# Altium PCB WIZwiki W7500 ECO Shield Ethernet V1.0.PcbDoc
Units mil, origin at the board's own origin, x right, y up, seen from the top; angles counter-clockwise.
Board outline 2814.96 x 1259.84 mil, 2 copper layers (Top Layer, Bottom Layer); 18 components, 48 nets, 133 pads, 48 vias.
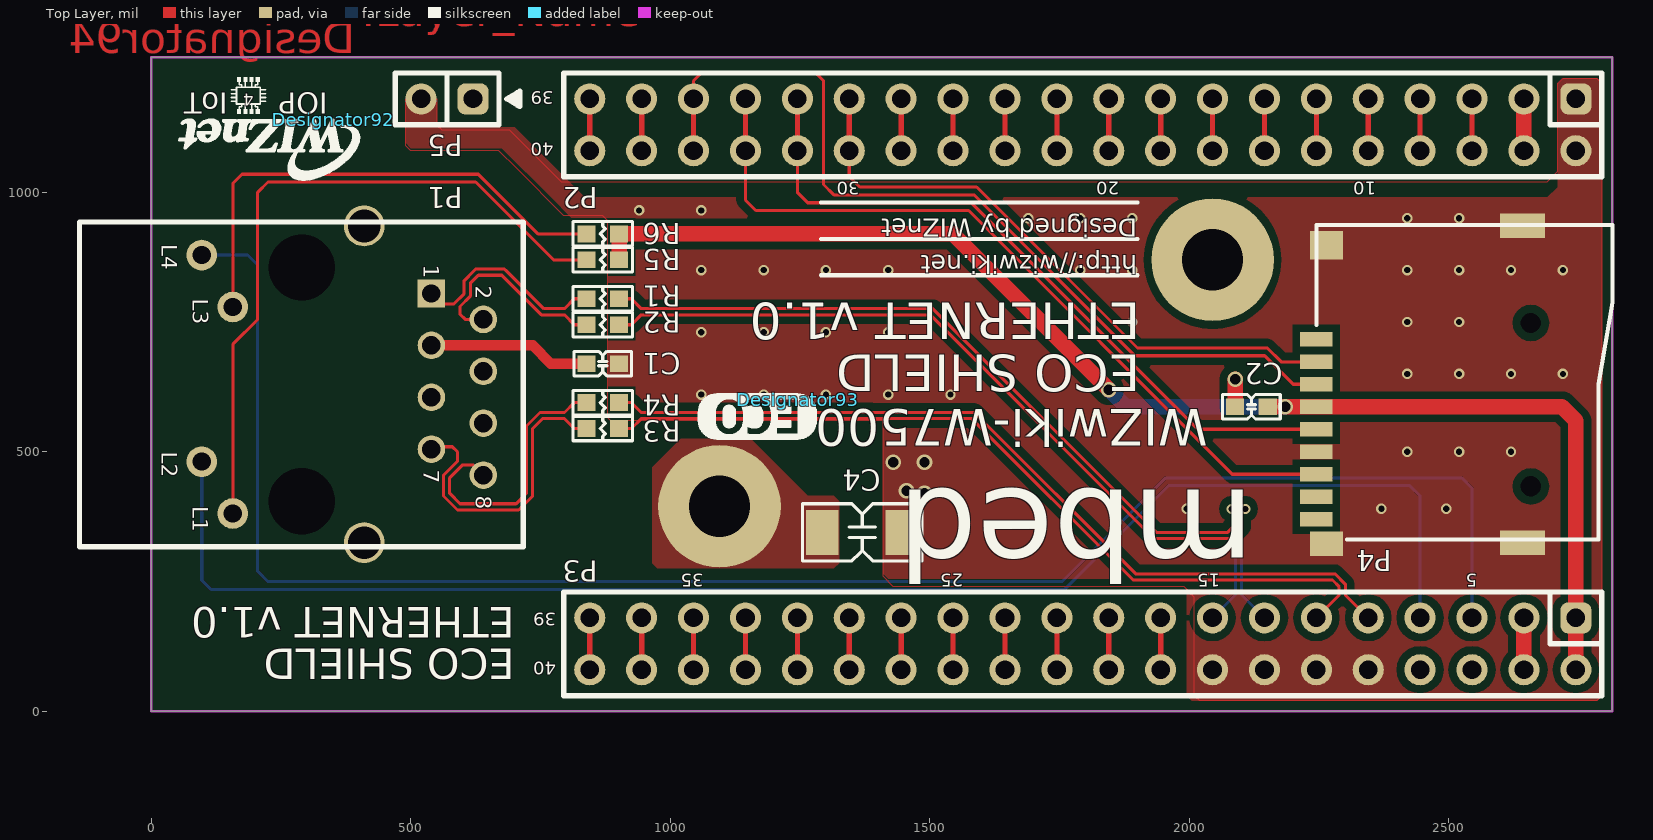
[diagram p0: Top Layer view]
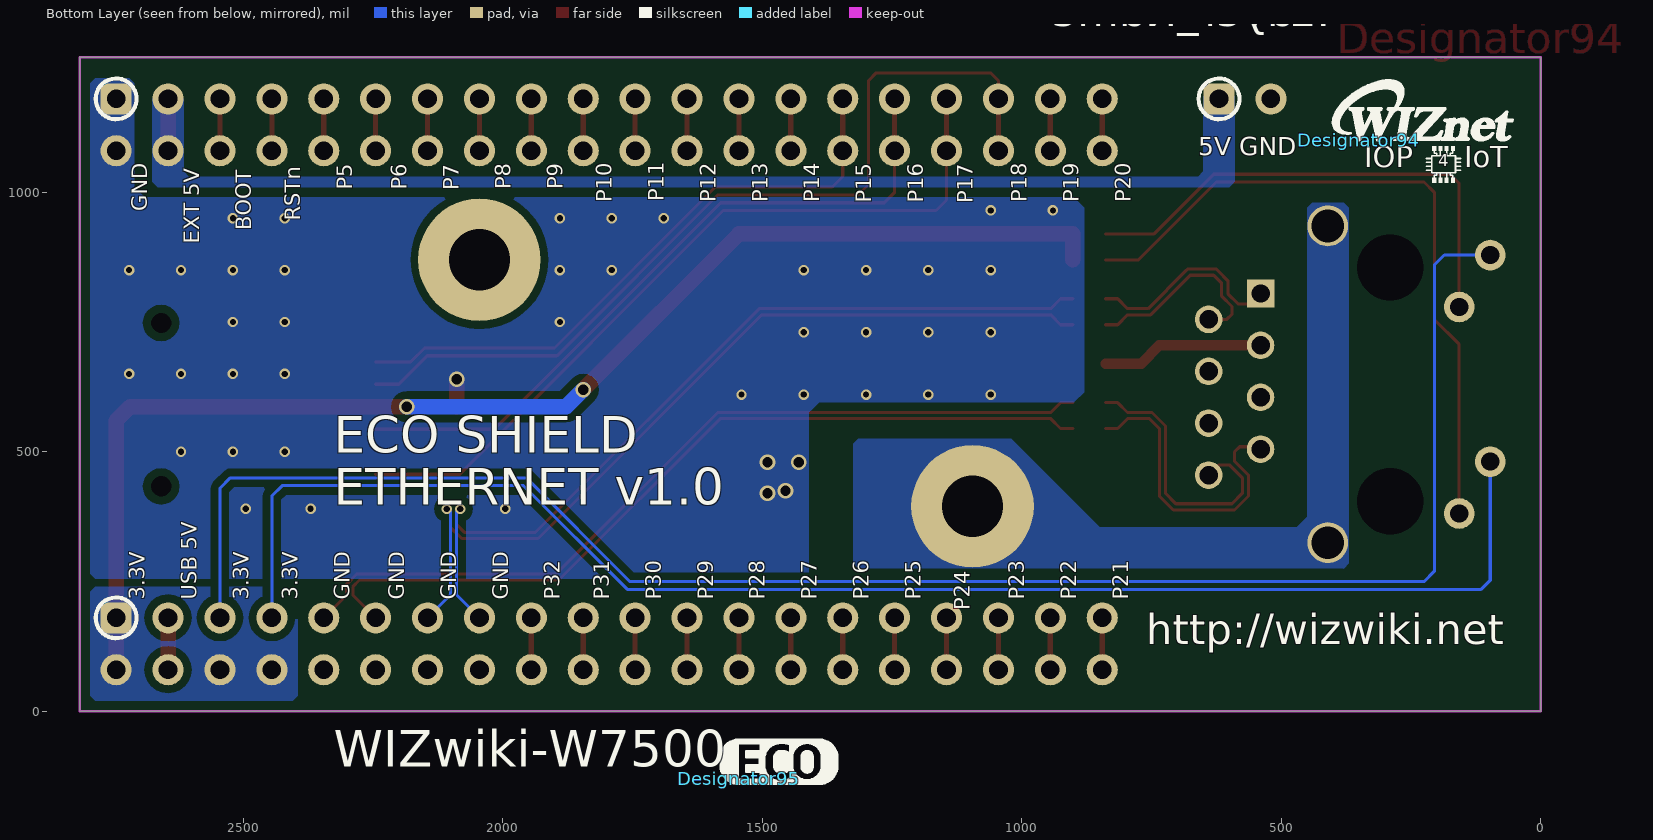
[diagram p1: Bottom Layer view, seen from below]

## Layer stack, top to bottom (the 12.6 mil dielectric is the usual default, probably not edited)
Top Solder: solder mask 0.4, Solder Resist, Dk 3.5
Top Layer: signal copper 1.4
Dielectric1: core 12.6, FR-4, Dk 4.8
Bottom Layer: signal copper 1.4
Bottom Solder: solder mask 0.4, Solder Resist, Dk 3.5

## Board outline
0,1259.84 2814.96,1259.84 2814.96,0 0,0

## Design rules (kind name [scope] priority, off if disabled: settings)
Clearance [All] p1: gap=6
DiffPairsRouting [All] p1: maxlimit=10 minlimit=5 mostfreqgap=6 toplayer_minwidth=15 toplayer_maxwidth=15 toplayer_prefwidth=15 bottomlayer_minwidth=15 bottomlayer_maxwidth=15 bottomlayer_prefwidth=15 maxuncoupledlength=500
HoleSize [All] p1: absolutevalues=TRUE maxlimit=160 minlimit=1 maxpercent=80.000 minpercent=20.000
PlaneClearance [All] p1: clearance=15
PlaneConnect [All] p1: planeconnectstyle=Direct reliefexpansion=20 reliefentries=4 reliefconductorwidth=10 reliefairgap=10
PolygonConnect PolygonConnect_2 [IsPad vs IsNamedPolygon('Top Layer-GND') Or  IsNamedPolygon('Bottom Layer-GND')] p1: connectstyle=Relief reliefconductorwidth=15 reliefentries=4 polygonreliefangle="90 Angle" airgapwidth=15
PolygonConnect PolygonConnect_1 [IsVia] p2: connectstyle=Direct reliefconductorwidth=10 reliefentries=4 polygonreliefangle="90 Angle" airgapwidth=10
PolygonConnect [All] p3: connectstyle=Direct reliefconductorwidth=10 reliefentries=4 polygonreliefangle="90 Angle" airgapwidth=10
RoutingVias [All] p1: holewidth=12 width=20 viastyle="Through Hole" minholewidth=12 minwidth=20 maxholewidth=20 maxwidth=30
SolderMaskExpansion [All] p1: expansion=0
UnpouredPolygon [All] p1: allowunpoured=FALSE
Width [All] p1: maxlimit=100 minlimit=4 preferedwidth=10
25 further rules are at their usual default settings.

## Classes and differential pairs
differential pair T: +T_P -T_N
differential pair R: +R_P -R_N
differential pair MDI_T: +MDI_T_P -MDI_T_N
differential pair MDI_R: +MDI_R_P -MDI_R_N

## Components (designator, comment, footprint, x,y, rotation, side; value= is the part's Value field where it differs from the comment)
C1 "0.1uF" CAP-0603 869.68,669.69 r180 top
C2 "0.1uF" CAP-0603 2119.68,586.61 r0 top locked
C4 "1n/2KV" CAP-1808 1369.68,344.69 r180 top
Designator92 "Comment" LOGO-WIZNET(SMALL-1) 350,1140 r180 top
Designator93 "Comment" LOGO-ECO 1245,600.32 r180 top
Designator94 "Comment" LOGO-WIZNET(SMALL-1) 350,1100 r180 bottom
Designator95 "Comment" LOGO-ECO 1545,-130 r180 bottom
P1 "RB1-125BAG1A" RJ45-125BAG1A 289.96,629.92 r270 top locked
P2 "Header 20X2" IDC-2X20 2744.68,1179.92 r180 top locked
P3 "Header 20X2" IDC-2X20 2744.68,179.92 r180 top locked
P4 "7MSDP-B0-1012" 7MSDP-B0-1012 2244.68,629.92 r90 top locked
P5 "2.54mm Pin Header" IDC-1X2 619.68,1179.92 r180 top locked
R1 "33R" RES-0603 869.68,794.69 r180 top
R2 "33R" RES-0603 869.68,744.69 r180 top
R3 "33R" RES-0603 869.68,544.69 r180 top
R4 "33R" RES-0603 869.68,594.69 r180 top
R5 "330R" RES-0603 869.68,869.69 r180 top
R6 "330R" RES-0603 869.68,919.69 r180 top

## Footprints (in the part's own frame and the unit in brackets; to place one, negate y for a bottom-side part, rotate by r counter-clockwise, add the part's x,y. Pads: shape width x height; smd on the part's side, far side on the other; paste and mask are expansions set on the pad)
7MSDP-B0-1012 [mm] "Micro SD Card Socket"
  rect 0.7x1.6 smd: 1(2.2,0) 2(1.1,0) 3(0,0) 4(-1.1,0) 5(-2.2,0) 6(-3.3,0) 7(-4.4,0) 8(-5.5,0) 9(-6.6,0)
  rect 1.2x1.6 smd: 10(-7.8,-0.5)
  rect 1.4x1.6 smd: 11(6.8,-0.5)
  rect 1.2x2.2 smd: 12(-7.75,-10.1) 13(7.75,-10.1)
  round 0.8 hole 1: ""(-5,-10.5) ""(3,-10.5)
  silkscreen extent -7.6,-14.5 7.8,0, body extent -8,-14.45 8,0.8, height 1.85
CAP-0603 [mm] "Ceramic CAP 0603(1608)"
  rect 0.89x0.82 smd: 1(-0.8,0) 2(0.8,0)
  silkscreen extent -1.41,-0.6 1.41,0.6, body extent -0.93,-0.41 0.93,0.41, height 0.81
CAP-1808 [mm] "Ceramic CAP 1808(4520)"
  rect 1.6x2.2 smd: 1(-1.95,0) 2(1.95,0)
  silkscreen extent -2.92,-1.4 2.92,1.4, body extent -2.25,-1.02 2.25,1.01, height 2
IDC-1X2 [mil]
  rrect50% 60x60 hole 36: 1(0,0)
  round 60 hole 36: 2(100,0)
  silkscreen extent -90,-50 150,50, body extent -49,-49 151,51, height 336
IDC-2X20 [mil]
  rrect50% 60x60 hole 36: 1(0,0)
  round 60 hole 36: 2(0,100) 3(100,0) 4(100,100) 5(200,0) 6(200,100) 7(300,0) 8(300,100) 9(400,0) 10(400,100) 11(500,0) 12(500,100) 13(600,0) 14(600,100) 15(700,0) 16(700,100) 17(800,0) 18(800,100) 19(900,0) 20(900,100) 21(1000,0) 22(1000,100) 23(1100,0) 24(1100,100) 25(1200,0) 26(1200,100) 27(1300,0) 28(1300,100) 29(1400,0) 30(1400,100) 31(1500,0) 32(1500,100) 33(1600,0) 34(1600,100) 35(1700,0) 36(1700,100) 37(1800,0) 38(1800,100) 39(1900,0) 40(1900,100)
  silkscreen extent -50,-50 1950,150, body extent -35,-50 1934,150, height 335
LOGO-ECO [mil]
  silkscreen extent -35,-10 190,75
LOGO-WIZNET(SMALL-1) [mil]
  silkscreen extent -50,-82 296,115
RES-0603 [mm] "RES-0603"
  rect 0.89x0.82 smd: 1(-0.8,0) 2(0.8,0)
  silkscreen extent -1.45,-0.6 1.45,0.6, body extent -0.82,-0.41 0.82,0.41, height 0.46
RJ45-125BAG1A [mm]
  round 1.5 hole 0.89: L1(6.325,-3.38) L2(3.785,-4.9) L3(-3.785,-3.38) L4(-6.325,-4.9)
  rect 1.35x1.35 hole 0.9: R1(-4.445,6.34)
  round 1.35 hole 0.9: R2(-3.175,8.88) R3(-1.905,6.34) R4(-0.635,8.88) R5(0.635,6.34) R6(1.905,8.88) R7(3.175,6.34) R8(4.445,8.88)
  round 2 hole 1.6: R9(-7.75,3.05) R10(7.75,3.05)
  round 1.8 hole 3.25: ""(-5.715,0) ""(5.715,0)
  silkscreen extent -7.95,-10.89 7.95,10.83, body extent -8.03,-10.8 7.97,10.5, height 13.1

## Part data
C1 C2: library part CAP-0603, "Ceramic CAP 0603(1608)"
C4: library part CAP-1808, "Ceramic CAP 1808(4520)"
P1: library part "RJ-45 MAGNETICS AND LEDS RB1-125BAG1A"
P2 P3: "Header, 20-Pin, Dual row, 2.54mm"
P4: "Micro SD Card Socket"
P5: library part MHDR1X2, "Header, 2-Pin"
R1 R2 R3 R4 R5 R6: library part RES-0603, "RES-0603"

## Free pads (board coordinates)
  round 236.22 hole 118.11: ""(1094.68,394.69) ""(2044.68,869.69)

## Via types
v1: diameter 20, hole 12, Top Layer to Bottom Layer, tented both sides, 41 vias
v2: diameter 30, hole 20, Top Layer to Bottom Layer, tented both sides, 7 vias

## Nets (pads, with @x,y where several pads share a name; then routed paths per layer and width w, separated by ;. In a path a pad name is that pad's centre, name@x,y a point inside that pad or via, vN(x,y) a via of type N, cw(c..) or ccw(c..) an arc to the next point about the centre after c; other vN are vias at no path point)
3.3V: C2.2 P3.1 P3.2 P3.6 P3.8 P4.4 R5.1 R6.1 | length 2555.9
  Top Layer w30: R5.1 R6.1 1544.68,919.69 v2(1844.68,619.69) ; C2.2 v2(2184.68,586.61) P4.4 2717.76,586.61 2744.68,559.69 P3.1 P3.2
  Bottom Layer w30: v2(1844.68,619.69) 1877.76,586.61 v2(2184.68,586.61)
AIN0: P3.21 P3.22 | length 100
  Top Layer w10: P3.22 P3.21
AIN1: P3.23 P3.24 | length 100
  Top Layer w10: P3.24 P3.23
AIN2: P3.25 P3.26 | length 100
  Top Layer w10: P3.26 P3.25
AIN3: P3.27 P3.28 | length 100
  Top Layer w10: P3.28 P3.27
AIN6: P3.29 P3.30 | length 100
  Top Layer w10: P3.30 P3.29
AIN7: P3.31 P3.32 | length 100
  Top Layer w10: P3.32 P3.31
BOOT0: P2.5 P2.6 | length 100
  Top Layer w10: P2.6 P2.5
CHGND: C4.2 P1.R9 P1.R10 pad.@1094.68,394.69
ETH_LED0: P1.L4 P3.5 | length 3394.8
  Bottom Layer w6: P1.L4 185.43,878.94 204.68,859.69 204.68,269.69 224.68,249.69 1754.68,249.69 1954.68,449.69 2524.68,449.69 2544.68,429.69 P3.5
ETH_LED3: P1.L2 P3.7 | length 2909.4
  Bottom Layer w6: P1.L2 97.05,252.32 114.68,234.69 1759.68,234.69 1959.68,434.69 2424.68,434.69 2444.68,414.69 P3.7
EXT_5V: P2.3 P2.4 P5.1 | length 100
  Top Layer w30: P2.4 P2.3
GND: C1.1 C2.1 C4.1 P2.1 P2.2 P3.10 P3.12 P3.14 P3.16 P4.6 P4.10 P4.11 P4.12 P4.13 P5.2 | length 53.4
  Top Layer w30: C2.1 v2(2088.19,640)
  other v1: 1995,390 2370,390 2495,390 2419.68,500 2519.68,500 2619.68,500 1059.68,610 1179.68,610 1299.68,610 1419.68,610 1539.68,610 2419.68,650 2519.68,650 2619.68,650 2719.68,650 1059.68,730 1179.68,730 1299.68,730 1419.68,730 1889.68,750 2419.68,750 2519.68,750 1059.68,850 1179.68,850 1299.68,850 1419.68,850 1789.68,850 1889.68,850 2419.68,850 2519.68,850 2619.68,850 2719.68,850 1689.68,950 1789.68,950 1889.68,950 2419.68,950 2519.68,950 939.68,965 1059.68,965
  other v2: 1489.68,420 1455,425 1429.68,480 1489.68,480
MDI_R_N: P3.9 R4.1 | length 1627.5
  Top Layer w6: R4.1 924.96,594.69 943.96,575.69 1330,575.69 1585.66,575.69 1896.66,264.69 2280.66,264.69 2300.68,244.66 2300.68,223.92 P3.9
MDI_R_P: P3.11 R3.1 | length 1607.6
  Top Layer w6: R3.1 924.96,544.69 943.96,563.69 1334.97,563.69 1580.68,563.69 1891.68,252.69 2275.68,252.69 2288.68,239.69 2288.68,223.92 P3.11
MDI_T_N: P3.13 R2.1 | length 1665
  Top Layer w6: R2.1 924.96,744.69 943.96,763.69 1500.68,763.69 1931.68,332.69 2078.66,332.69 2100.68,354.71 2100.68,382.69 v1(2107.68,389.69)
  Bottom Layer w6: v1(2107.68,389.69) 2105.68,389.69 2100.68,384.69 2100.68,223.92 P3.13
MDI_T_P: P3.15 R1.1 | length 1645.1
  Top Layer w6: R1.1 924.96,794.69 943.96,775.69 1505.66,775.69 1936.66,344.69 2073.68,344.69 2088.68,359.69 2088.68,382.69 v1(2081.68,389.69)
  Bottom Layer w6: P3.15 2088.68,223.92 2088.68,384.69 2083.68,389.69 v1(2081.68,389.69)
MISO0: P2.13 P2.14 | length 100
  Top Layer w10: P2.14 P2.13
MISO1: P2.33 P2.34 P4.7 | length 1513.9
  Top Layer w6: P2.34 1144.68,984.69 1164.68,964.69 1574.68,964.69 2082.68,456.69 P4.7
  Top Layer w10: P2.34 P2.33
MOSI0: P2.15 P2.16 | length 100
  Top Layer w10: P2.16 P2.15
MOSI1: P2.35 P2.36 P4.3 | length 1706.8
  Top Layer w6: P2.35 1044.68,1214.69 1060,1230 1280,1230 1295,1215 1295,1015 1315,995 1585,995 1895,685 2145,685 2200.08,629.92 P4.3
  Top Layer w10: P2.36 P2.35
NetC1_2: C1.2 P1.R3 | length 313.2
  Top Layer w20: P1.R3 734.45,704.92 769.68,669.69 C1.2
NetP1_L1: P1.L1 R5.2 | length 1342.5
  Top Layer w6: P1.L1 156.89,706.89 204.68,754.69 204.68,999.69 224.68,1019.69 624.68,1019.69 774.68,869.69 R5.2
NetP1_L3: P1.L3 R6.2 | length 974.3
  Top Layer w6: P1.L3 156.89,1016.89 174.68,1034.69 629.68,1034.69 744.68,919.69 R6.2
PC_06: P3.19 P3.20 | length 100
  Top Layer w10: P3.20 P3.19
PC_07: P3.17 P3.18 | length 100
  Top Layer w10: P3.18 P3.17
R_N: P1.R8 R4.2 | length 542.1
  Top Layer w6: P1.R8 619.8,474.69 599.68,474.69 574.68,449.69 574.68,419.69 594.68,399.69 702.68,399.69 722.68,419.69 722.68,549.66 748.71,575.69 795.96,575.69 814.96,594.69 R4.2
R_P: P1.R7 R3.2 | length 596
  Top Layer w6: P1.R7 544.33,509.69 579.68,509.69 589.68,499.69 589.68,481.66 562.68,454.66 562.68,414.71 589.71,387.69 707.66,387.69 734.68,414.71 734.68,544.69 753.68,563.69 795.96,563.69 814.96,544.69 R3.2
RESET_SW: P2.7 P2.8 | length 100
  Top Layer w10: P2.8 P2.7
SCL0: P2.17 P2.18 | length 100
  Top Layer w10: P2.18 P2.17
SCL1: P2.39 P2.40 | length 100
  Top Layer w10: P2.40 P2.39
SCLK0: P2.11 P2.12 | length 100
  Top Layer w10: P2.12 P2.11
SCLK1: P2.31 P2.32 P4.5 | length 1369.3
  Top Layer w6: P2.32 1244.68,999.69 1264.68,979.69 1579.68,979.69 2016.06,543.31 P4.5
  Top Layer w10: P2.32 P2.31
SDA0: P2.19 P2.20 | length 100
  Top Layer w10: P2.20 P2.19
SDA1: P2.37 P2.38 | length 100
  Top Layer w10: P2.38 P2.37
SSEL0: P2.9 P2.10 | length 100
  Top Layer w10: P2.10 P2.9
SSEL1: P2.29 P2.30 P4.2 | length 1197.5
  Top Layer w6: P2.30 1344.68,1030.31 1365,1010 1590,1010 1900,700 2150,700 2176.77,673.23 P4.2
  Top Layer w10: P2.30 P2.29
T_N: P1.R2 R2.2 | length 386.5
  Top Layer w6: P1.R2 604.45,754.92 594.68,764.69 594.68,779.69 614.68,799.69 614.68,824.69 630,840 675,840 751.31,763.69 795.96,763.69 814.96,744.69 R2.2
T_P: P1.R1 R1.2 | length 389
  Top Layer w6: P1.R1 559.8,784.69 582.71,784.69 602.68,804.66 602.68,829.66 621.51,848.49 625.03,852 679.97,852 683.49,848.49 756.29,775.69 795.96,775.69 814.96,794.69 R1.2
U_CTS0: P2.21 P2.22 | length 100
  Top Layer w10: P2.22 P2.21
U_CTS1: P3.39 P3.40 | length 100
  Top Layer w10: P3.40 P3.39
U_RTS0: P2.23 P2.24 | length 100
  Top Layer w10: P2.24 P2.23
U_RTS1: P3.37 P3.38 | length 100
  Top Layer w10: P3.38 P3.37
U_RXD0: P2.27 P2.28 | length 100
  Top Layer w10: P2.28 P2.27
U_RXD1: P3.33 P3.34 | length 100
  Top Layer w10: P3.34 P3.33
U_TXD0: P2.25 P2.26 | length 100
  Top Layer w10: P2.26 P2.25
U_TXD1: P3.35 P3.36 | length 100
  Top Layer w10: P3.36 P3.35
USB_5V: P3.3 P3.4 | length 100
  Top Layer w30: P3.4 P3.3
pads on no net: P1. P1.R4 P1.R5 P1.R6 P4. P4.1 P4.8 P4.9

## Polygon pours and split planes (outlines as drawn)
GND on Top Layer "Top Layer-NET" (solid, remove dead copper, shelved, pour order 10): 489.68,1180 549.68,1180 549.68,1130 559.68,1120 589.68,1120 689.68,1120 739.68,1070 789.68,1020 929.68,1020 2689.68,1020 2709.68,1040 2709.68,1210 2719.68,1220 2784.68,1220 2794.68,1210 2794.68,1185 2794.68,30 2784.68,20 2684.68,20 2019.68,20 2009.68,30 2009.68,79.92 2009.68,220 1989.68,240 1939.68,240 1429.68,240 1409.68,260 1409.68,560 884.68,560 879.68,565 879.68,675 879.68,945 869.68,955 844.68,955 794.68,955 704.68,1045 669.68,1080 524.68,1080 499.68,1080 489.68,1090
CHGND on Top Layer "Keep-Out Layer-No Net" (solid, pour order 12): 1325,285 1315,275 975,275 965,285 965,470 1020,525 1155,525 1260,420 1265,415 1315,415 1325,405
GND on Top Layer "Keep-Out Layer-No Net" (solid, pour order 11): 2719.68,1220 2709.68,1210 2709.68,1010 2689.68,990 2605,990 835,990 725,1100 700,1125 560,1125 550,1135 550,1180 490,1180 490,1095 500,1085 520,1085 675,1085 770,990 810,950 865,950 870,950 880,940 880,605 890,595 940,595 1390,595 1410,575 1410,264.69 1419.68,255 1980,255 1995,240 1995,225 1995,30 2005,20 2055,20 2785,20 2795,30 2795,50 2795,1209.69 2784.68,1220
EXT_5V on Bottom Layer "Top Layer-NET" (solid, remove dead copper, pour order 8): 649.68,1185 589.68,1185 589.68,1020 599.68,1010 2664.68,1010 2674.68,1020 2674.68,1180 2614.68,1180 2614.68,1040 2604.68,1030 659.68,1030 649.68,1040
3.3V on Bottom Layer "Top Layer-NET" (solid, remove dead copper, pour order 9): 2794.68,30 2784.68,20 2759.68,20 2404.68,20 2394.68,30 2394.68,70 2394.68,230 2404.68,240 2479.68,240 2784.68,240 2794.68,230
CHGND on Bottom Layer "Top Layer-NET" (solid, remove dead copper, pour order 14): 379.68,979.69 369.68,969.69 369.68,284.69 379.68,274.69 380,275 444.68,275 1314.37,275 1314.68,274.69 1324.68,284.69 1324.68,335 1324.68,515 1314.68,525 1019.68,525 989.68,495 849.37,354.69 469.68,354.69 449.68,374.69 449.68,969.69 439.68,979.69
GND on Bottom Layer "Top Layer-NET" (solid, remove dead copper, pour order 13): 1419.68,255 1409.68,265 1409.68,575 1389.68,595 899.68,595 879.68,615 879.68,970 899.68,990 2689.68,990 2709.68,1010 2709.68,1210 2719.68,1220 2784.68,1220 2794.68,1210 2794.68,265 2784.68,255

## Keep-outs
Keep-Out Layer:
  the board outline again, w5
  text ".Layer_Name" at 414.96,1654.92 h60

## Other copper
Top Layer:
  text ".Layer_Name" at 404.96,1319.92 h60
Bottom Layer:
  text ".Layer_Name" at 404.96,1319.92 h60

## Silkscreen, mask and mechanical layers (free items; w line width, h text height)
Top Overlay:
  lines w7.87: 1290,840 1900,840 ; 1290,910 1900,910 ; 1290,980 1900,980
  text ".Layer_Name" at 414.96,1654.92 h60
  text "39" at 775,1195 h25 r180
  text "40" at 775,1095 h25 r180
  text "Designed by WIZnet" at 1900,960 h60 r180
  text "http://wizwiki.net" at 1900,890 h60 r180
  text "ETHERNET v1.0" at 1905,810 h120 r180
  text "ECO SHIELD" at 1905,710 h120 r180
  text "WIZwiki-W7500" at 2035,605 h120 r180
  text "mbed" at 2125,485 h300 r180
  text "ETHERNET v1.0" at 700,220 h100 r180
  text "39" at 780,190 h25 r180
  text "ECO SHIELD" at 700,140 h100 r180
  text "40" at 780,95 h25 r179.9
Bottom Overlay:
  text ".Layer_Name" at 404.96,1319.92 h60
  text "5V GND" at 660,1060 h60
  text "P9" at 1875,1005.79 h50 r270
  text "P8" at 1975,1005.42 h50 r270
  text "P6" at 2175,1005 h50 r270
  text "P5" at 2280,1004.91 h50 r270
  text "P7" at 2075,1003.8 h50 r270
  text "P11" at 1680,983.1 h50 r270
  text "P19" at 880,980.93 h50 r270
  text "P18" at 980,980.56 h50 r270
  text "P14" at 1380,980.88 h50 r270
  text "P13" at 1480,980.84 h50 r270
  text "P20" at 780,980.33 h50 r270
  text "P16" at 1180,980.14 h50 r270
  text "P15" at 1280,980.05 h50 r270
  text "P12" at 1580,980.38 h50 r270
  text "P10" at 1780,980.33 h50 r270
  text "P17" at 1085,978.94 h50 r270
  text "GND" at 2675,963.28 h50 r270
  text "RSTn" at 2380,944.8 h50 r270
  text "BOOT" at 2475,927.15 h50 r270
  text "EXT 5V" at 2575,900.96 h50 r270
  text "ECO SHIELD" at 2325,475 h120
  text "ETHERNET v1.0" at 2325,375 h120
  text "P21" at 785,215 h50 r270
  text "P22" at 885,215 h50 r270
  text "P23" at 985,215 h50 r270
  text "P25" at 1185,215 h50 r270
  text "P26" at 1285,215 h50 r270
  text "P27" at 1385,215 h50 r270
  text "P28" at 1485,215 h50 r270
  text "P29" at 1585,215 h50 r270
  text "P30" at 1685,215 h50 r270
  text "P31" at 1785,215 h50 r270
  text "P32" at 1880,215 h50 r270
  text "GND" at 1980,215 h50 r270
  text "GND" at 2080,215 h50 r270
  text "GND" at 2180,215 h50 r270
  text "GND" at 2285,215 h50 r270
  text "3.3V" at 2385,215 h50 r270
  text "3.3V" at 2480,215 h50 r270
  text "USB 5V" at 2580,215 h50 r270
  text "3.3V" at 2680,215 h50 r270
  text "P24" at 1090,195 h50 r270
  text "http://wizwiki.net" at 760,110 h100
  text "WIZwiki-W7500" at 2325,-130 h120
Top Paste:
  text ".Layer_Name" at 404.96,1319.92 h60
Bottom Paste:
  text ".Layer_Name" at 404.96,1319.92 h60
Top Solder:
  text ".Layer_Name" at 414.96,1654.92 h60
Bottom Solder:
  text ".Layer_Name" at 404.96,1319.92 h60
Drill Guide:
  text ".Layer_Name" at 414.96,1654.92 h60
Mechanical 2:
  lines w5: 2964.96,599.92 3994.96,599.92 ; 2964.96,689.92 3994.96,689.92 ; 0,0 2814.96,0 2814.96,1259.84 0,1259.84 0,0 ; 2914.96,316.11 ccw(c2942.96,316.11) 2942.96,288.11 4084.96,288.11 ccw(c4084.96,316.11) 4112.96,316.11 4112.96,1030.11 ccw(c4084.96,1030.11) 4084.96,1058.11 2942.96,1058.11 ccw(c2942.96,1030.11) 2914.96,1030.11 2914.96,316.11
  text "BOARD NAME : WIZwiki-W7500ECO Shield Ethernet" at 34.96,1764.92 h60
  text "VERSION : V1.0" at 34.96,1654.92 h60
  text "SIZE : 32mmX71.5mmX1.6T" at 34.96,1544.92 h60
  text "GERBER DATE : 2015.09.08" at 34.96,1424.92 h60
  text "LAYER :" at 34.96,1319.92 h60
  text "Layer Stack Up Detail for :" at 2964.96,959.92 h40
  text "WIZwiki-W7500ECO" at 2964.96,859.92 h50
  text "Shield Ethernet V1.0.PcbDoc" at 2964.96,759.92 h50
  text "Layer Name : 2L 1.6T" at 2964.96,629.92 h40
  text "Top Layer" at 2964.96,479.92 h60
  text "Bottom Layer" at 2964.96,349.92 h60
  text "KS-TECH artwork" at 2914.96,118.11 h200
Drill Drawing:
  text ".Legend" at 2010,1725 h30
  text ".Layer_Name" at 414.96,1654.92 h60

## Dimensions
0,1259.84 to 0,0 on Mechanical 1
0,0 to 2814.96,0 on Mechanical 1
2744.68,1079.92 to 2744.68,179.92 on Mechanical 1
2744.68,1179.92 to 2744.68,79.92 on Mechanical 1
519.68,1179.92 to 0,1259.84 on Mechanical 1
-138.78,942.91 to -138.78,316.93 on Mechanical 1
2744.68,1179.92 to 844.68,1179.92 on Mechanical 1
0,0 to 1094.68,394.69 on Mechanical 1
1094.68,394.69 to 2044.68,869.69 on Mechanical 1
2814.96,1259.84 to 2044.68,869.69 on Mechanical 1
2044.68,869.69 to 1094.68,394.69 on Mechanical 1
1094.68,394.69 to 2814.96,0 on Mechanical 1
2044.68,869.69 to 2814.96,0 on Mechanical 1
